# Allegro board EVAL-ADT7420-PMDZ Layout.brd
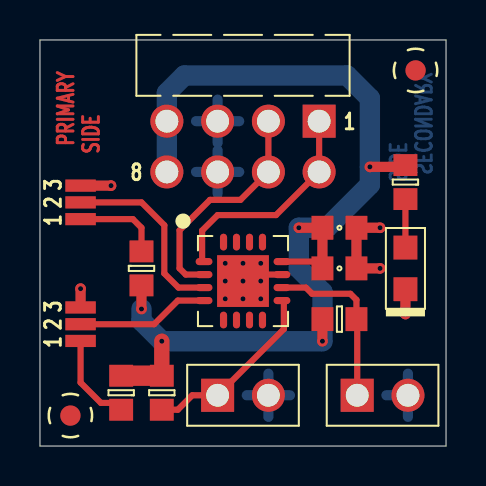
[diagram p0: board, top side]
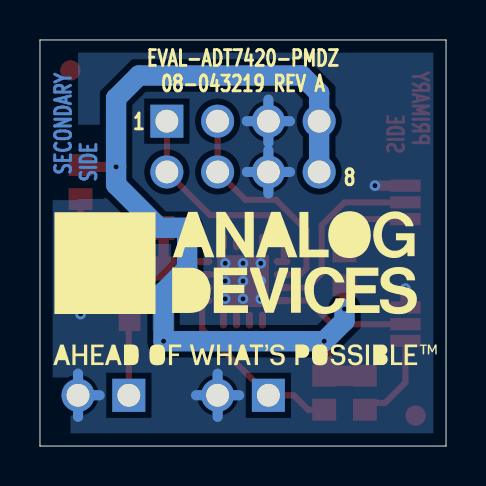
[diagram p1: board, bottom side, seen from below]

Outline 20.32 x 20.32 mm; copper layers: TOP, BOTTOM. Coordinates in mm from the lower left corner of the outline.
Outline path: 0,20.32 0,0 20.32,0 20.32,20.32 0,20.32

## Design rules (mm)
constraint set DEFAULT: min track width 0.305

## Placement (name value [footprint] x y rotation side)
C1  10uF  [C0603]  14.99 8.89 180 top
C2  0.1uF  [C0603]  14.99 10.92 180 top
DS1  SML-LXT0805GW-TR  [LXT0805]  18.29 8.89 90 top
JP1  3PIN_SOLDER_JUMPER  [JPRSLD03]  2.03 6.1 90 top
JP2  3PIN_SOLDER_JUMPER  [JPRSLD03]  2.03 12.19 90 top
NOREF  -  []  66.55 82.17 0 top
NOREF#2  -  []  20.32 0 90 top
NOREF#3  -  []  -76.2 -93.98 0 top
NOREF#4  -  []  -76.2 -93.98 0 top
NOREF#5  -  []  -76.2 -93.98 0 top
NOREF#6  -  []  0 20.32 0 top
NOREF#7  -  [unnamed#2]  18.8 18.8 0 top
NOREF#8  -  []  6.35 13.72 0 top
NOREF#9  -  []  36.2 271.02 0 top
NOREF#10  -  []  236.22 -20.32 0 top
NOREF#11  -  []  254 293.37 0 top
NOREF#12  -  []  0 0 0 top
NOREF#13  -  []  6.35 13.72 0 top
NOREF#14  -  [unnamed#2]  1.52 1.52 0 top
NOREF#15  -  []  254 255.27 270 top
NOREF#16  -  []  0 0 0 top
NOREF#17  -  []  20.32 0 0 top
NOREF#18  -  []  0 20.32 0 top
NOREF#19  -  []  10.03 7.87 180 bottom
P1  TSW-104-25-F-D-RA  [CNHDRRA2X4H240_B]  13.97 16.26 180 top
P4  TSW-102-08-G-S  [CNSAMTEC1X2H330LD36]  17.14 2.54 0 top
P5  TSW-102-08-G-S  [CNSAMTEC1X2H330LD36]  10.16 2.54 0 top
R1  200  [R0603]  18.29 13.21 90 top
R2  10K  [R0603]  4.06 2.67 90 top
R3  10K  [R0603]  5.08 8.89 270 top
R4  10K  [R0603]  14.99 6.35 180 top
R5  10K  [R0603]  6.1 2.67 90 top
U1  ADT7420UCPZ-RL7  [QFN16_4X4_PAD2_6X2_6]  10.16 8.26 270 top

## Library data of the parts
C1 = CAP: Tolerance: 20; User Part Number: UPN; alternate symbols: (); part number: CAP_SM-10UF,6.3V,20,E007143,C0603; tolerance: 20
C2 = CAP: Tolerance: 10; User Part Number: UPN; alternate symbols: (); part number: CAP_SM-0.1UF,16V,10,E015036,C0603; tolerance: 10
DS1 = DIOLED: Tolerance: N/A; User Part Number: UPN; alternate symbols: (); part number: DIOLED_SM-SML-LXT0805GW-TR,N/A,N/A,E005318,LXT0805; tolerance: N/A
JP1 JP2 = NC3P_JMPR: Tolerance: N/A; User Part Number: UPN; alternate symbols: (); part number: NC3P_JMPR_SM-3PIN_SOLDER_JUMPER,E005606,JPRSLD03; tolerance: N/A
P1 = CN8P_V2: User Part Number: UPN; Tolerance: N/A; alternate symbols: (); part number: CN8P_V2_TH-TSW-104-25-F-D-RA,E018544,CNHDRRA2X4H240_B; tolerance: N/A
P4 P5 = CN2P: User Part Number: UPN; Tolerance: N/A; alternate symbols: (); part number: CN2P_TH-TSW-102-08-G-S,E006296,CNSAMTEC1X2H330LD36; tolerance: N/A
R1 = RES: Tolerance: 1; User Part Number: UPN; alternate symbols: (R0603L); part number: RES_SM-200,E007248,1/10W,1,R0603; tolerance: 1
R2-R5 = RES: Tolerance: 1; User Part Number: UPN; alternate symbols: (R0603L); part number: RES_SM-10K,E022442,1/4W,1,R0603; tolerance: 1
U1 = ADT7420: Tolerance: N/A; User Part Number: UPN; alternate symbols: (); part number: ADT7420_SM-ADT7420UCPZ-RL7,E013789,QFN16_4X4_PAD2_6X2_6; tolerance: N/A

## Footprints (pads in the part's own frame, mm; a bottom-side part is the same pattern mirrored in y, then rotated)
C0603
  rect 1.092x1.194 smd: 1(-0.851,0) 2(0.851,0)
CNHDRRA2X4H240_B
  rect 1.651x1.651 hole 1.143: 1(0,0)
  round 1.651 hole 1.143: 2(0,2.54) 3(2.54,0) 4(2.54,2.54) 5(5.08,0) 6(5.08,2.54) 7(7.62,0) 8(7.62,2.54)
CNSAMTEC1X2H330LD36
  rect 1.651x1.651 hole 1.143: 1(-1.27,0)
  round 1.651 hole 1.143: 2(1.27,0)
JPRSLD03
  rect 0.61x1.524 smd: 1(-0.838,0) 2(0,0) 3(0.838,0)
LXT0805
  rect 1.194x1.194 smd: A(1.041,0) C(-1.041,0)
QFN16_4X4_PAD2_6X2_6
  oval 0.356x0.838 smd: 1(-0.975,-1.95) 2(-0.325,-1.95) 3(0.325,-1.95) 4(0.975,-1.95) 9(0.975,1.95) 10(0.325,1.95) 11(-0.325,1.95) 12(-0.975,1.95)
  oval 0.838x0.356 smd: 5(1.95,-0.975) 6(1.95,-0.325) 7(1.95,0.325) 8(1.95,0.975) 13(-1.95,0.975) 14(-1.95,0.325) 15(-1.95,-0.325) 16(-1.95,-0.975)
  rect 2.591x2.591 smd: PAD(0,0)
R0603
  rect 1.092x1.194 smd: 1(-0.851,0) 2(0.851,0)
unnamed#2
  round 1.016 smd: (0,0)

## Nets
DGND: C1.1 C2.1 DS1.C JP1.3 JP2.3 P1.5 P1.6 P4.2(N2) P5.2(N2) U1.11 U1.PAD
VDD: C1.2(N2) C2.2(N2) P1.7 P1.8(VCC2) R1.2(N2) R2.2(N2) R3.2(N2) R4.2(N2) R5.2(N2) U1.12(VDD)
SCL: P1.1 P1.2 U1.1
SDA: P1.3 P1.4 U1.2
UNNAMED_1_ADT7420_I1_A0: JP2.2(COM) U1.3
UNNAMED_1_ADT7420_I1_A1: JP1.2(COM) U1.4
UNNAMED_1_ADT7420_I1_CT: P4.1 R4.1 U1.10
UNNAMED_1_ADT7420_I1_INT: P5.1 R5.1 U1.9
UNNAMED_1_DIOLED_I16_P: DS1.A(P) R1.1
UNNAMED_1_NC3PJMPR_I43_A: JP1.1 R2.1
UNNAMED_1_NC3PJMPR_I44_A: JP2.1 R3.1

Pads without a net: U1 5 6 7 8 13 14 15 16

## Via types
v1: diameter 0.533, hole 0.254, TOP to BOTTOM, 19 vias

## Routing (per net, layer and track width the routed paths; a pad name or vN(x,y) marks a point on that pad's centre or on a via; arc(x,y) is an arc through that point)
DGND: length 25.8
  TOP w0.305: v1(11.05,9.14) 11.05,8.88 11.35,8.58 U1.11 12.2,8.58
  TOP w0.508: v1(3.56,13.03) JP2.3 ; v1(18.29,6.6) DS1.C ; v1(17.02,10.92) C2.1 C1.1 v1(17.02,8.89) ; v1(2.03,7.87) JP1.3
  BOTTOM w0.508: 18.41,1.46 P4.2 ; P4.2 18.41,3.62 ; P4.2 17.33,2.54 ; P5.2 12.51,2.54 ; P5.2 10.35,2.54 ; P5.2 11.43,1.46 ; P5.2 11.43,3.62 ; 7.81,16.26 P1.5 ; P1.5 9.97,16.26 ; P1.5 8.89,17.34 ; P1.5 8.89,15.18 ; P1.6 8.89,14.8 ; P1.6 8.89,12.64 ; P1.6 7.81,13.72 ; P1.6 9.97,13.72
  vias: v1(9.27,9.14) v1(9.27,8.26) v1(9.27,7.37) v1(10.16,9.14) v1(10.16,8.26) v1(10.16,7.37) v1(11.05,8.26) v1(11.05,7.37)
VDD: length 53.1
  TOP w0.305: 12.2,9.23 13.79,9.23 C1.2
  TOP w0.508: C1.2 C2.2 v1(12.95,10.92) ; v1(16.51,13.97) 18.2,13.97 R1.2 ; R4.2 v1(14.14,5.25) ; v1(5.08,6.86) R3.2
  TOP w0.762: v1(6.1,5.25) R5.2
  TOP w1.016: R2.2 R5.2
  BOTTOM w1.016: P1.8 P1.7 6.35,17.67 7.23,18.54 15.37,18.54 16.51,17.4 v1(16.51,13.97) 16.51,13.08 14.35,10.92 v1(12.95,10.92) 12.95,8.89 14.14,7.71 v1(14.14,5.25) v1(6.1,5.25) 5.08,6.26 v1(5.08,6.86)
SCL: length 11.2
  TOP w0.305: 8.12,9.23 8.12,10.78 8.89,11.56 11.81,11.56 P1.2 P1.1
SDA: length 11.4
  TOP w0.305: 8.12,8.58 7.29,8.58 6.99,8.89 6.99,10.79 8.51,12.32 10.03,12.32 P1.4 P1.3
UNNAMED_1_ADT7420_I1_A0: length 9.3
  TOP w0.305: 8.12,7.93 6.93,7.93 6.22,8.64 6.22,11.05 5.08,12.19 JP2.2
UNNAMED_1_ADT7420_I1_A1: length 6.6
  TOP w0.305: 8.12,7.28 6.9,7.28 5.71,6.1 JP1.2
UNNAMED_1_ADT7420_I1_CT: length 8.7
  TOP w0.305: P4.1 15.88,6.31 R4.1 15.84,7.32 15.53,7.62 13.62,7.62 13.31,7.93 12.2,7.93
UNNAMED_1_ADT7420_I1_INT: length 9.2
  TOP w0.305: R5.1 6.9,1.82 7.62,2.54 P5.1 12.2,5.85 12.2,7.28
UNNAMED_1_DIOLED_I16_P: length 2.4
  TOP w0.305: DS1.A R1.1
UNNAMED_1_NC3PJMPR_I43_A: length 4.7
  TOP w0.305: R2.1 3.72,2.16 3.05,2.16 2.03,3.18 JP1.1
UNNAMED_1_NC3PJMPR_I44_A: length 4.4
  TOP w0.305: JP2.1 4.65,11.35 5.08,10.92 R3.1

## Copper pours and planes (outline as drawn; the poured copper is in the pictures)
DGND on BOTTOM: 0.63,0.63 0.63,19.68 19.69,19.68 19.69,3.43 18.8,3.43 18.8,0.63

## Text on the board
BOTTOM: SIDE
Ref Des/Silkscreen Bottom: EVAL-ADT7420-PMDZ
TOP: SIDE
DIMENSION: REF | DIA MAX | SEE NOTE 15
PAGE_OUTLINE: CUSTOMER EVAL BOARD Z
User.11: ASSEMBLY NOTES: | 1. JP1 AND JP2 ARE SOLDER BRIDGES. PINS 2 AND 3 OF JP1 AND JP2 SHOULD BE SHORTED BY SOLDERING DURING ASSEMBLY
User.15: 15.    INDICATED VIAS TO BE PLUGGED AND COVERED WITH SOLDERMASK | AT SECONDARY SIDE
User.45: FIGURE | SIZE | 10.0 | 10.01 | 45.0 | PLATED | FINISHED HOLES IN MILS | ALL UNITS ARE IN MILS | QTY | 10 | 9 | 12 | TOLERANCE/NOTES
